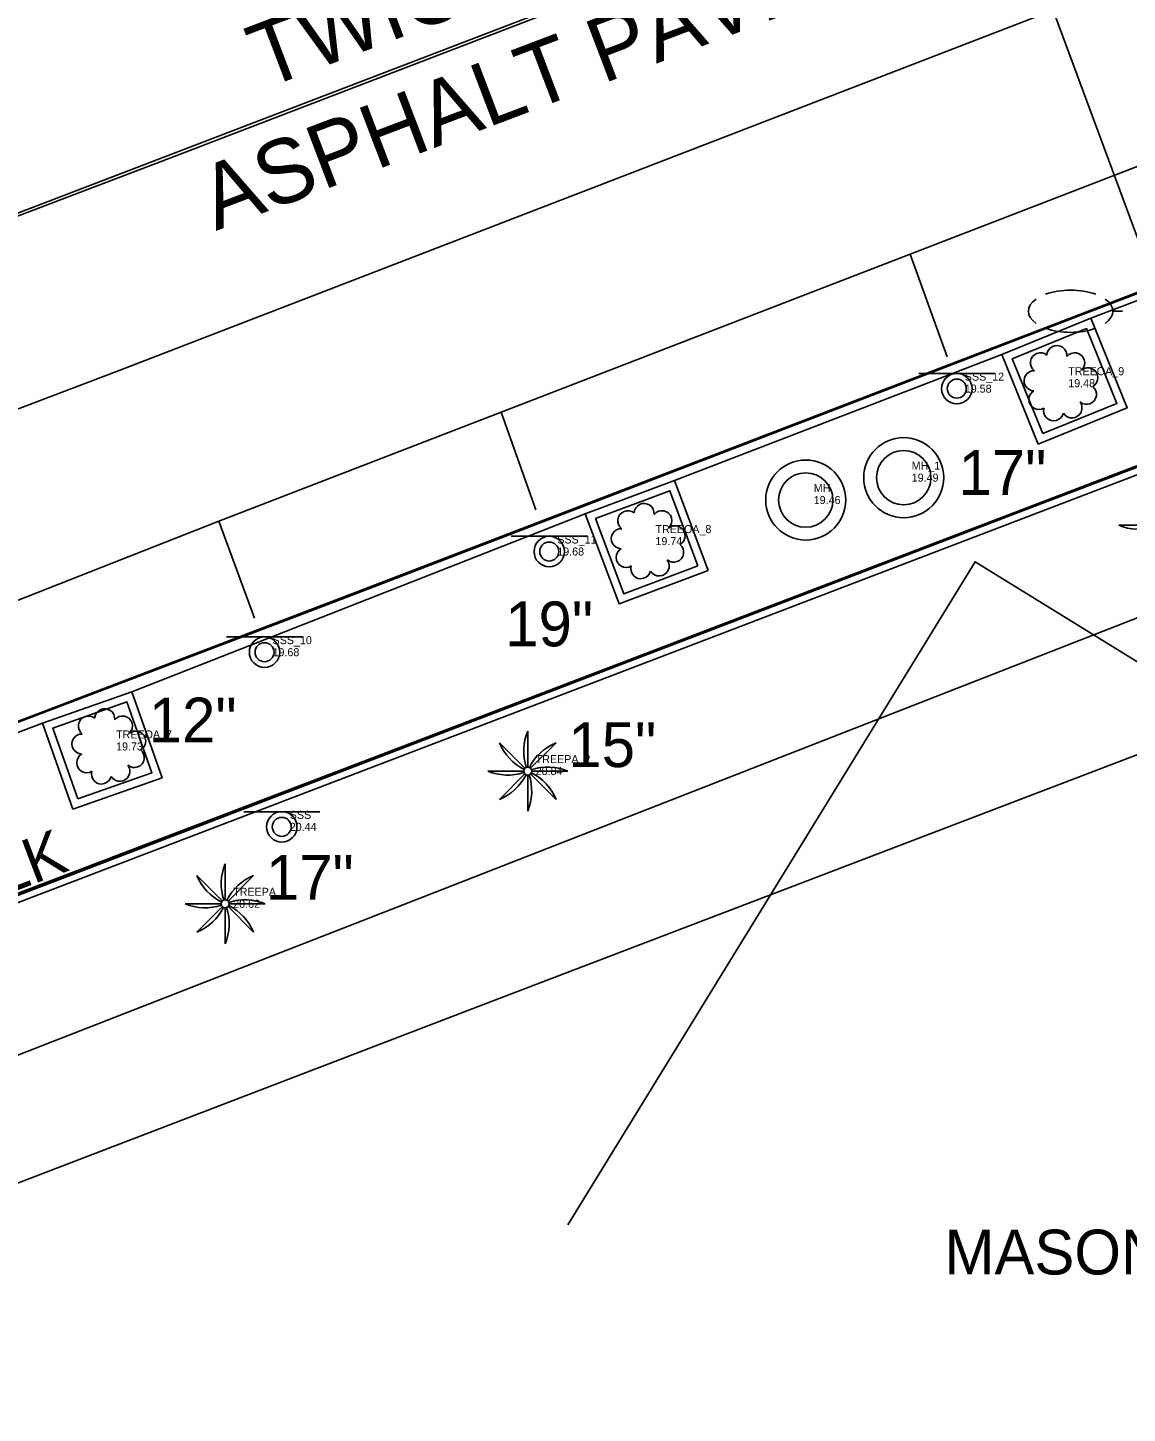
# Model space of a CAD drawing. Extents: x 509744 to 512285, y 1314862 to 1316822.
# Drawn here: x 510410.5 to 510479.2, y 1315310 to 1315396.5 of the extents above; entities that cross this region are included whole.
import ezdxf

# ---------------------------------------------------------------- set-up
doc = ezdxf.new("R2010")
doc.units = 0
for name, color, linetype in [('BaselineSurvey', 7, 'Continuous'), ('Building_ep', 7, 'Continuous'), ('CGBack_ep', 7, 'Continuous'), ('CGFace_ep', 7, 'Continuous'), ('ElecAer_ep', 7, 'Continuous'), ('Luminaire_ep', 7, 'Continuous'), ('ManholeUnknown_ep', 7, 'Continuous'), ('PavtAsphalt_ep', 7, 'Continuous'), ('PavtAsphaltCrown_ep', 7, 'Continuous'), ('PMRK_ep', 7, 'Continuous'), ('RWLine_ep', 7, 'Continuous'), ('SidewalkBack_ep', 7, 'Continuous'), ('SignSingle_ep', 7, 'Continuous'), ('TextElevLabel', 7, 'Continuous'), ('TextPtLabel', 7, 'Continuous'), ('TextTopoLabel_ep', 7, 'Continuous'), ('TreeOak_ep', 7, 'Continuous'), ('TreePalm_ep', 7, 'Continuous'), ('Wall_ep', 7, 'Continuous')]:
    doc.layers.add(name, color=color, linetype=linetype)

msp = doc.modelspace()

# ---------------------------------------------------------------- linework, layer by layer
at = {"layer": 'BaselineSurvey'}
msp.add_line((509756.059, 1315134.106), (510956.768, 1315594.743), dxfattribs=at)
at = {"layer": 'Building_ep'}
msp.add_lwpolyline([(510444.29, 1315321.724), (510469.732, 1315363.166), (510517.064, 1315333.974), (510533.864, 1315323.605)], dxfattribs=at)
at = {"layer": 'CGBack_ep'}
for p, q in [((510450.95, 1315368.252), (510471.412, 1315376.122)), ((510417.048, 1315355.049), (510445.382, 1315366.154)), ((510391.102, 1315345.456), (510411.477, 1315353.083))]:
    msp.add_line(p, q, dxfattribs=at)
msp.add_lwpolyline([(510379.508, 1315330.168), (510381.362, 1315330.893), (510386.834, 1315333.037), (510480.241, 1315368.749), (510525.361, 1315386.071)], dxfattribs=at)
at = {"layer": 'CGFace_ep'}
msp.add_line((510476.971, 1315378.388), (510501.338, 1315387.656), dxfattribs=at)
for points in [[(510352.81, 1315331.142), (510354.379, 1315331.951), (510359.641, 1315333.957), (510383.105, 1315342.938), (510429.84, 1315360.709), (510476.515, 1315378.641), (510521.226, 1315395.726)], [(510379.306, 1315330.779), (510381.148, 1315331.462), (510386.647, 1315333.533), (510433.358, 1315351.369), (510480.089, 1315369.154), (510525.358, 1315386.597)]]:
    msp.add_lwpolyline(points, dxfattribs=at)
for points in [[(510473.686, 1315370.527), (510479.245, 1315372.793), (510476.971, 1315378.388), (510471.412, 1315376.122)], [(510473.961, 1315371.178), (510478.594, 1315373.067), (510476.696, 1315377.737), (510472.063, 1315375.848)], [(510453.066, 1315362.629), (510447.499, 1315360.531), (510445.382, 1315366.154), (510450.95, 1315368.252)], [(510452.422, 1315362.92), (510447.79, 1315361.175), (510446.026, 1315365.863), (510450.658, 1315367.608)], [(510413.375, 1315347.71), (510418.946, 1315349.676), (510417.048, 1315355.049), (510411.477, 1315353.083)], [(510413.68, 1315348.347), (510418.309, 1315349.98), (510416.743, 1315354.412), (510412.115, 1315352.779)]]:
    msp.add_lwpolyline(points, close=True, dxfattribs=at)
at = {"layer": 'ElecAer_ep'}
msp.add_line((510459.752, 1315437.864), (510481.571, 1315378.822), dxfattribs=at)
at = {"layer": 'Luminaire_ep'}
msp.add_line((510478.946, 1315378.822), (510478.346, 1315378.822), dxfattribs=at)
for start_param, end_param in [(5.668326, 6.898045), (4.075781, 5.348997), (2.526733, 3.756452), (0.934187, 2.207405)]:
    msp.add_ellipse((510475.706, 1315378.822), major_axis=(-2.64, 0), ratio=0.5, start_param=start_param, end_param=end_param, dxfattribs=at)
at = {"layer": 'ManholeUnknown_ep'}
for centre, radius in [((510465.277, 1315368.424), 2.5), ((510465.277, 1315368.424), 1.7), ((510459.156, 1315367.026), 2.5), ((510459.156, 1315367.026), 1.7)]:
    msp.add_circle(centre, radius, dxfattribs=at)
at = {"layer": 'PavtAsphalt_ep'}
msp.add_lwpolyline([(510351.184, 1315329.899), (510352.81, 1315331.142), (510354.374, 1315331.964), (510383.094, 1315342.967), (510429.812, 1315360.784), (510476.495, 1315378.696), (510521.169, 1315395.881)], dxfattribs=at)
at = {"layer": 'PavtAsphaltCrown_ep'}
msp.add_lwpolyline([(510325.988, 1315352.728), (510372.689, 1315370.593), (510419.418, 1315388.38), (510466.088, 1315406.325)], dxfattribs=at)
at = {"layer": 'PMRK_ep'}
for p, q in [((510465.671, 1315382.386), (510467.998, 1315375.965)), ((510440.118, 1315372.515), (510442.301, 1315366.404)), ((510422.49, 1315365.706), (510424.721, 1315359.637))]:
    msp.add_line(p, q, dxfattribs=at)
for points in [[(510329.975, 1315342.271), (510376.644, 1315360.09), (510415.985, 1315375.014), (510489.962, 1315403.569), (510512.083, 1315411.986)], [(510422.49, 1315365.706), (510440.118, 1315372.515), (510465.671, 1315382.386), (510483.048, 1315389.099), (510507.51, 1315398.548), (510515.781, 1315401.743)], [(510405.117, 1315358.881), (510422.49, 1315365.706)]]:
    msp.add_lwpolyline(points, dxfattribs=at)
at = {"layer": 'RWLine_ep'}
msp.add_line((509817.131, 1315115.31), (510540.744, 1315392.412), dxfattribs=at)
at = {"layer": 'SidewalkBack_ep'}
msp.add_lwpolyline([(510358.093, 1315322.401), (510381.133, 1315331.501), (510386.631, 1315333.575), (510433.349, 1315351.393), (510480.057, 1315369.237)], dxfattribs=at)
at = {"layer": 'SignSingle_ep'}
for p, q in [((510466.22, 1315374.937), (510470.97, 1315374.937)), ((510440.756, 1315364.759), (510445.506, 1315364.759)), ((510422.968, 1315358.468), (510427.718, 1315358.468)), ((510424.044, 1315347.552), (510428.794, 1315347.552))]:
    msp.add_line(p, q, dxfattribs=at)
for centre, radius in [((510468.595, 1315373.987), 0.95), ((510468.595, 1315373.987), 0.594), ((510443.131, 1315363.809), 0.95), ((510443.131, 1315363.809), 0.594), ((510425.343, 1315357.518), 0.95), ((510425.343, 1315357.518), 0.594), ((510426.419, 1315346.602), 0.95), ((510426.419, 1315346.602), 0.594)]:
    msp.add_circle(centre, radius, dxfattribs=at)
at = {"layer": 'TreeOak_ep'}
for centre, radius, start, end in [((510473.823, 1315375.605), 0.624, 50.71855, 233.08403), ((510474.846, 1315376.051), 0.629, 355.39425, 176.65487), ((510475.959, 1315375.603), 0.627, 315.08978, 140.68326), ((510476.782, 1315374.663), 0.626, 299.43541, 127.26128), ((510473.419, 1315374.482), 0.625, 87.30955, 269.56183), ((510473.722, 1315373.311), 0.626, 119.4469, 301.0197), ((510476.699, 1315373.631), 0.623, 229.28724, 51.20251), ((510474.646, 1315372.606), 0.625, 164.28711, 346.27665), ((510475.79, 1315372.782), 0.628, 211.18773, 36.81995), ((510449.056, 1315366.182), 0.629, 355.39425, 176.65487), ((510448.032, 1315365.736), 0.624, 50.71855, 233.08403), ((510450.168, 1315365.734), 0.627, 315.08978, 140.68326), ((510447.628, 1315364.612), 0.625, 87.30955, 269.56183), ((510450.991, 1315364.793), 0.626, 299.43541, 127.26128), ((510447.931, 1315363.442), 0.626, 119.4469, 301.0197), ((510450.908, 1315363.762), 0.623, 229.28724, 51.20251), ((510449.999, 1315362.913), 0.628, 211.18773, 36.81995), ((510448.855, 1315362.736), 0.625, 164.28711, 346.27665), ((510415.355, 1315353.351), 0.629, 355.39425, 176.65487), ((510414.332, 1315352.905), 0.624, 50.71855, 233.08403), ((510416.468, 1315352.903), 0.627, 315.08978, 140.68326), ((510413.928, 1315351.781), 0.625, 87.30955, 269.56183), ((510417.291, 1315351.962), 0.626, 299.43541, 127.26128), ((510414.231, 1315350.611), 0.626, 119.4469, 301.0197), ((510417.208, 1315350.931), 0.623, 229.28724, 51.20251), ((510416.299, 1315350.082), 0.628, 211.18773, 36.81995), ((510415.155, 1315349.905), 0.625, 164.28711, 346.27665)]:
    msp.add_arc(centre, radius, start, end, dxfattribs=at)
at = {"layer": 'TreePalm_ep'}
for p, q in [((510478.71, 1315365.449), (510480.96, 1315365.449)), ((510441.608, 1315350.266), (510440.017, 1315351.857)), ((510441.785, 1315350.339), (510441.785, 1315352.589)), ((510441.962, 1315350.266), (510443.553, 1315351.857)), ((510439.285, 1315350.089), (510441.535, 1315350.089)), ((510440.017, 1315348.322), (510441.608, 1315349.913)), ((510441.785, 1315347.589), (510441.785, 1315349.839)), ((510443.553, 1315348.322), (510441.962, 1315349.913)), ((510442.035, 1315350.089), (510444.285, 1315350.089)), ((510422.884, 1315342.044), (510422.884, 1315344.294)), ((510422.708, 1315341.97), (510421.117, 1315343.561)), ((510423.061, 1315341.97), (510424.652, 1315343.561)), ((510420.384, 1315341.794), (510422.634, 1315341.794)), ((510421.117, 1315340.026), (510422.708, 1315341.617)), ((510422.884, 1315339.294), (510422.884, 1315341.544)), ((510424.652, 1315340.026), (510423.061, 1315341.617)), ((510423.134, 1315341.794), (510425.384, 1315341.794))]:
    msp.add_line(p, q, dxfattribs=at)
for centre in [(510441.785, 1315350.089), (510422.884, 1315341.794)]:
    msp.add_circle(centre, 0.25, dxfattribs=at)
for centre, start, end in [((510479.96, 1315368.449), 247.38014, 288.21141), ((510443.023, 1315353.095), 202.38014, 243.21141), ((510444.785, 1315351.339), 157.38014, 198.21141), ((510444.79, 1315348.852), 112.38014, 153.21141), ((510443.035, 1315347.089), 67.38014, 108.21141), ((510440.535, 1315353.089), 247.38014, 288.21141), ((510438.78, 1315351.327), 292.38014, 333.21141), ((510438.785, 1315348.839), 337.38014, 18.21141), ((510440.548, 1315347.084), 22.38014, 63.21141), ((510425.884, 1315343.044), 157.38014, 198.21141), ((510424.122, 1315344.799), 202.38014, 243.21141), ((510425.89, 1315340.556), 112.38014, 153.21141), ((510421.634, 1315344.794), 247.38014, 288.21141), ((510419.879, 1315343.031), 292.38014, 333.21141), ((510419.884, 1315340.544), 337.38014, 18.21141), ((510421.647, 1315338.788), 22.38014, 63.21141), ((510424.134, 1315338.794), 67.38014, 108.21141)]:
    msp.add_arc(centre, 3.25, start, end, dxfattribs=at)
at = {"layer": 'Wall_ep'}
for points in [[(510393.878, 1315318.189), (510439.297, 1315335.602), (510486.001, 1315353.457), (510525.56, 1315368.689)], [(510385.621, 1315322.855), (510436.606, 1315342.746), (510483.174, 1315360.962)]]:
    msp.add_lwpolyline(points, dxfattribs=at)

# ---------------------------------------------------------------- texts
at = {"layer": 'TextElevLabel'}
for s, p in [('19.48', (510475.558, 1315374.078)), ('19.58', (510469.095, 1315373.737)), ('19.49', (510465.777, 1315368.174)), ('19.46', (510459.656, 1315366.776)), ('19.68', (510443.631, 1315363.559)), ('19.74', (510449.767, 1315364.209)), ('19.68', (510425.843, 1315357.268)), ('19.73', (510416.067, 1315351.378)), ('20.84', (510442.285, 1315349.839)), ('20.44', (510426.919, 1315346.352)), ('20.62', (510423.384, 1315341.544))]:
    msp.add_text(s, height=0.5, dxfattribs=at).set_placement(p)
at = {"layer": 'TextPtLabel'}
for s, p in [('TREEOA_9', (510475.558, 1315374.828)), ('SSS_12', (510469.095, 1315374.487)), ('MH_1', (510465.777, 1315368.924)), ('MH', (510459.656, 1315367.526)), ('SSS_11', (510443.631, 1315364.309)), ('TREEOA_8', (510449.767, 1315364.959)), ('SSS_10', (510425.843, 1315358.018)), ('TREEOA_7', (510416.067, 1315352.128)), ('TREEPA_2', (510442.285, 1315350.589)), ('SSS', (510426.919, 1315347.102)), ('TREEPA_1', (510423.384, 1315342.294))]:
    msp.add_text(s, height=0.5, dxfattribs=at).set_placement(p)
at = {"layer": 'TextTopoLabel_ep'}
for s, height, rotation, p in [('TWIGGS STREET', 4, 20.81265, (510425.332, 1315392.691)), ('ASPHALT PAVEMENT', 4, 20.81265, (510422.305, 1315383.837)), ('CONCRETE SIDEWALK', 2.8, 20.86605, (510374.55, 1315329.159))]:
    msp.add_text(s, height=height, rotation=rotation, dxfattribs=at).set_placement(p)
for s, p in [('17"', (510468.698, 1315367.343)), ('19"', (510440.377, 1315357.886)), ('12"', (510418.108, 1315351.878)), ('15"', (510444.326, 1315350.339)), ('17"', (510425.425, 1315342.044)), ('MASONARY BUILDING', (510467.826, 1315318.632))]:
    msp.add_text(s, height=2.8, dxfattribs=at).set_placement(p)

doc.saveas('drawing.dxf')
